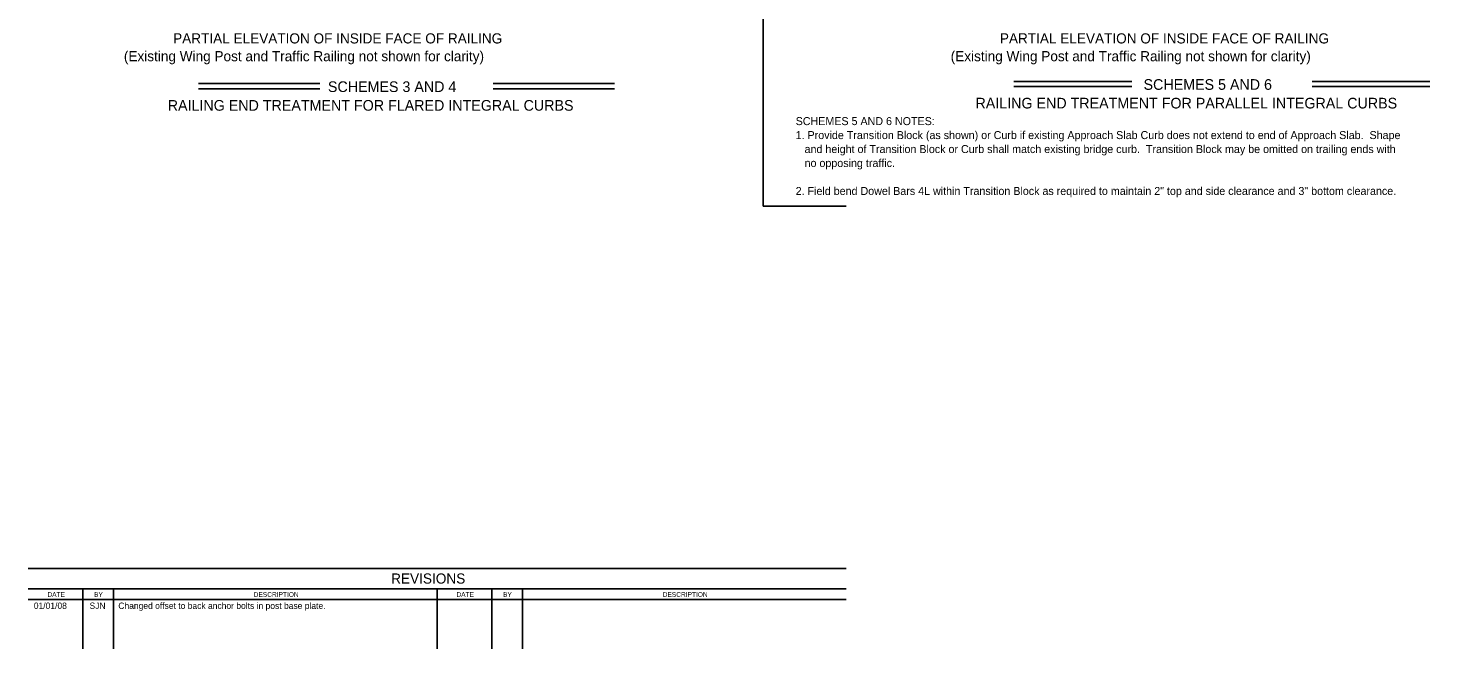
# Model space of a CAD drawing. Extents: x 21587 to 21659.1, y 56116.2 to 56157.3.
# Drawn here: x 21586.98 to 21622.3, y 56116.16 to 56131.8 of the extents above; entities that cross this region are included whole.
import ezdxf

# ---------------------------------------------------------------- set-up
doc = ezdxf.new("R2010")
doc.units = 0
for name, color, linetype in [('Border', 7, 'Continuous'), ('PlotBorder_dp', 7, 'Continuous'), ('SheetBorder_dp', 7, 'Continuous')]:
    doc.layers.add(name, color=color, linetype=linetype)

msp = doc.modelspace()

# ---------------------------------------------------------------- linework, layer by layer
at = {"layer": 'Border'}
for p, q in [((21607.59, 56118.19), (21586.978, 56118.19)), ((21607.59, 56117.675), (21586.978, 56117.675)), ((21588.355, 56117.675), (21588.355, 56116.16)), ((21589.128, 56117.675), (21589.128, 56116.16)), ((21597.284, 56117.675), (21597.284, 56116.16)), ((21598.661, 56117.675), (21598.661, 56116.16)), ((21599.434, 56117.675), (21599.434, 56116.16)), ((21586.978, 56117.402), (21607.59, 56117.402))]:
    msp.add_line(p, q, dxfattribs=at)
at = {"layer": 'PlotBorder_dp'}
for p, q in [((21605.502, 56153.256), (21605.502, 56127.317)), ((21594.329, 56130.405), (21591.272, 56130.405)), ((21598.698, 56130.405), (21601.755, 56130.405)), ((21614.793, 56130.46), (21611.821, 56130.46)), ((21614.793, 56130.327), (21611.821, 56130.327)), ((21619.333, 56130.46), (21622.304, 56130.46)), ((21619.333, 56130.327), (21622.304, 56130.327)), ((21594.329, 56130.271), (21591.272, 56130.271)), ((21598.698, 56130.271), (21601.755, 56130.271)), ((21607.59, 56127.317), (21605.502, 56127.317))]:
    msp.add_line(p, q, dxfattribs=at)

# ---------------------------------------------------------------- texts
for s, height, p in [('PARTIAL ELEVATION OF INSIDE FACE OF RAILING', 0.256, (21590.634, 56131.415)), ('PARTIAL ELEVATION OF INSIDE FACE OF RAILING', 0.256, (21611.467, 56131.415)), ('(Existing Wing Post and Traffic Railing not shown for clarity)', 0.256, (21589.393, 56130.967)), ('(Existing Wing Post and Traffic Railing not shown for clarity)', 0.256, (21610.227, 56130.967)), ('SCHEMES 3 AND 4', 0.2688, (21594.535, 56130.192)), ('SCHEMES 5 AND 6', 0.2688, (21615.087, 56130.247)), ('RAILING END TREATMENT FOR FLARED INTEGRAL CURBS', 0.2688, (21590.498, 56129.721)), ('RAILING END TREATMENT FOR PARALLEL INTEGRAL CURBS', 0.2688, (21610.852, 56129.777)), ('SCHEMES 5 AND 6 NOTES:', 0.2016, (21606.321, 56129.358)), ('1. Provide Transition Block (as shown) or Curb if existing Approach Slab Curb does not extend to end of Approach Slab.  Shape ', 0.2016, (21606.321, 56129.006)), ('   and height of Transition Block or Curb shall match existing bridge curb.  Transition Block may be omitted on trailing ends with ', 0.2016, (21606.321, 56128.654)), ('   no opposing traffic.', 0.2016, (21606.321, 56128.302)), ('2. Field bend Dowel Bars 4L within Transition Block as required to maintain 2" top and side clearance and 3" bottom clearance.', 0.2016, (21606.321, 56127.598))]:
    msp.add_text(s, height=height, dxfattribs=at).set_placement(p)
at = {"layer": 'SheetBorder_dp'}
for s, height, p in [('REVISIONS', 0.2567, (21596.127, 56117.806)), ('BY', 0.1201, (21588.642, 56117.472)), ('BY', 0.1201, (21598.948, 56117.472)), ('01/01/08', 0.16, (21587.124, 56117.169)), ('SJN', 0.16, (21588.527, 56117.169)), ('Changed offset to back anchor bolts in post base plate.', 0.16, (21589.253, 56117.169))]:
    msp.add_text(s, height=height, dxfattribs=at).set_placement(p)
for s, height, rotation, p in [('DATE', 0.1196, 359.8693, (21587.467, 56117.473)), ('DESCRIPTION', 0.12007, 0.0498, (21592.664, 56117.472)), ('DATE', 0.1196, 359.8693, (21597.773, 56117.473)), ('DESCRIPTION', 0.12007, 0.0498, (21602.971, 56117.472))]:
    msp.add_text(s, height=height, rotation=rotation, dxfattribs=at).set_placement(p)

doc.saveas('drawing.dxf')
